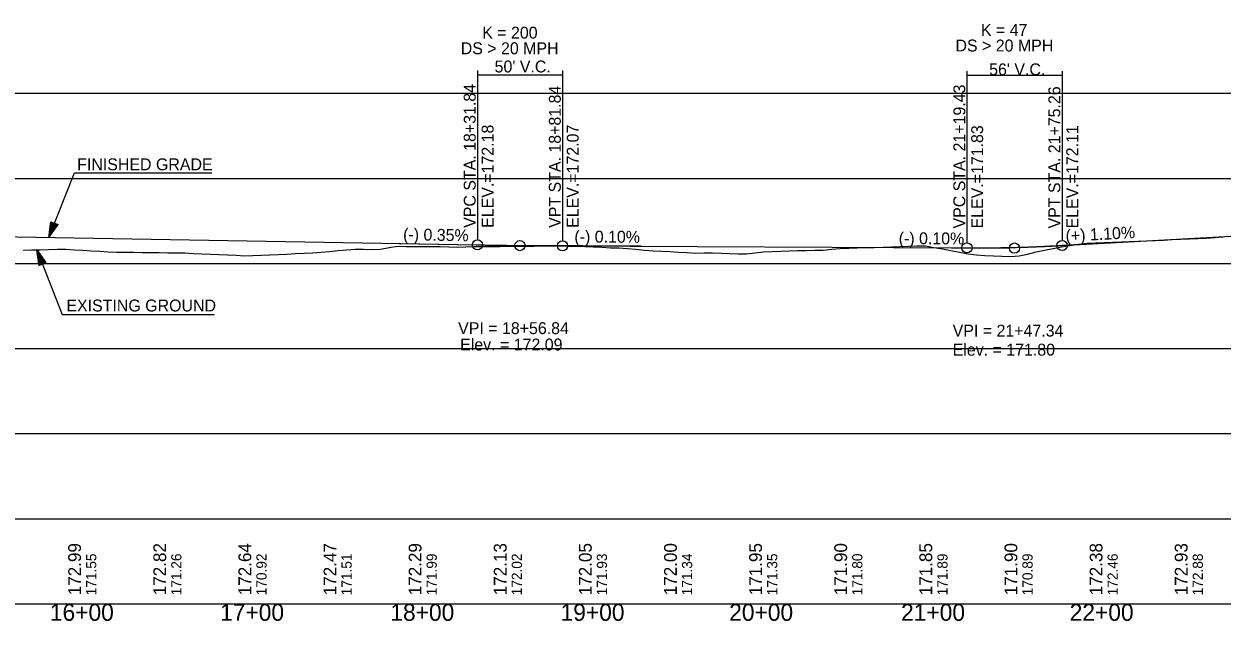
# Model space of a CAD drawing. Extents: x 69 to 2003113, y 512 to 837401.
# Drawn here: x 1891225 to 1891928, y 775879 to 776230 of the extents above; entities that cross this region are included whole.
import ezdxf

# ---------------------------------------------------------------- set-up
doc = ezdxf.new("R2010")
doc.units = 0
for name, color, linetype in [('BR_AUTO DIMENSION', 7, 'Continuous'), ('BR_BORDER LINES', 7, 'Continuous'), ('BR_CENTER LINE BASELINE', 7, 'Continuous'), ('BR_CONCRETE', 7, 'Continuous'), ('BR_GRID DOTS', 7, 'Continuous'), ('BR_GRID LINES', 7, 'Continuous'), ('BR_TEXT', 7, 'Continuous'), ('RD_HC_Points', 7, 'Continuous'), ('RD_PD_ALT1_TrvlWay', 7, 'Continuous'), ('RD_SHT_ID', 7, 'Continuous'), ('RD_SHT_IplotShp', 7, 'Continuous')]:
    doc.layers.add(name, color=color, linetype=linetype)

msp = doc.modelspace()

# ---------------------------------------------------------------- linework, layer by layer
at = {"layer": 'BR_AUTO DIMENSION'}
for p, q in [((1890659.14, 776189.14), (1892786.34, 776189.14)), ((1890659.14, 776139.14), (1892786.34, 776139.14)), ((1890659.14, 776089.14), (1892786.34, 776089.14)), ((1890659.14, 776039.14), (1892786.34, 776039.14)), ((1890659.14, 775989.14), (1892786.34, 775989.14)), ((1890659.14, 775939.14), (1892786.34, 775939.14)), ((1890659.14, 775889.14), (1892786.34, 775889.14))]:
    msp.add_line(p, q, dxfattribs=at)
at = {"layer": 'BR_BORDER LINES'}
for q in [(1892559.14, 775889.14), (1893259.14, 775889.14)]:
    msp.add_line((1890659.14, 775889.14), q, dxfattribs=at)
at = {"layer": 'BR_CENTER LINE BASELINE'}
for p, q in [((1891444.99, 776100.85), (1891512.98, 776099.66)), ((1891586.98, 776099.25), (1891518.98, 776099.59)), ((1891735.48, 776098.51), (1891803.48, 776098.17)), ((1891877.38, 776102.06), (1891809.48, 776098.32))]:
    msp.add_line(p, q, dxfattribs=at)
for centre in [(1891515.98, 776099.61), (1891806.48, 776098.16)]:
    msp.add_circle(centre, 3, dxfattribs=at)
at = {"layer": 'BR_GRID DOTS'}
for p, q in [((1891490.98, 776202.55), (1891490.98, 776103.05)), ((1891490.98, 776200.05), (1891540.98, 776200.05)), ((1891540.98, 776202.55), (1891540.98, 776102.48)), ((1891778.57, 776202.19), (1891778.57, 776101.3)), ((1891778.57, 776199.69), (1891834.4, 776199.69)), ((1891834.4, 776202.19), (1891834.4, 776102.69))]:
    msp.add_line(p, q, dxfattribs=at)
for centre in [(1891490.98, 776100.05), (1891540.98, 776099.48), (1891778.57, 776098.3), (1891834.4, 776099.69)]:
    msp.add_circle(centre, 3, dxfattribs=at)
at = {"layer": 'BR_GRID LINES'}
for p, q in [((1891834.4, 776099.69), (1892067.07, 776112.49)), ((1891084.14, 776107.17), (1891490.98, 776100.05)), ((1891540.98, 776099.48), (1891778.57, 776098.3))]:
    msp.add_line(p, q, dxfattribs=at)
for points in [[(1891490.98, 776100.05), (1891491.98, 776100.03), (1891492.98, 776100.01), (1891493.98, 776100), (1891494.98, 776099.98), (1891495.98, 776099.96), (1891496.98, 776099.95), (1891497.98, 776099.93), (1891498.98, 776099.91), (1891499.98, 776099.9), (1891500.98, 776099.88), (1891501.98, 776099.87), (1891502.98, 776099.85), (1891503.98, 776099.84), (1891504.98, 776099.83), (1891505.98, 776099.81), (1891506.98, 776099.8), (1891507.98, 776099.79), (1891508.98, 776099.77), (1891509.98, 776099.76), (1891510.98, 776099.75), (1891511.98, 776099.73), (1891512.98, 776099.72), (1891513.98, 776099.71), (1891514.98, 776099.7), (1891515.98, 776099.69), (1891516.98, 776099.68), (1891517.98, 776099.67), (1891518.98, 776099.65), (1891519.98, 776099.64), (1891520.98, 776099.63), (1891521.98, 776099.62), (1891522.98, 776099.61), (1891523.98, 776099.61), (1891524.98, 776099.6), (1891525.98, 776099.59), (1891526.98, 776099.58), (1891527.98, 776099.57), (1891528.98, 776099.56), (1891529.98, 776099.55), (1891530.98, 776099.55), (1891531.98, 776099.54), (1891532.98, 776099.53), (1891533.98, 776099.53), (1891534.98, 776099.52), (1891535.98, 776099.51), (1891536.98, 776099.51), (1891537.98, 776099.5), (1891538.98, 776099.49), (1891539.98, 776099.49), (1891540.98, 776099.48)], [(1891778.57, 776098.3), (1891779.68, 776098.29), (1891780.8, 776098.29), (1891781.92, 776098.29), (1891783.03, 776098.28), (1891784.15, 776098.29), (1891785.27, 776098.29), (1891786.38, 776098.29), (1891787.5, 776098.29), (1891788.62, 776098.3), (1891789.73, 776098.31), (1891790.85, 776098.32), (1891791.97, 776098.33), (1891793.08, 776098.34), (1891794.2, 776098.35), (1891795.32, 776098.36), (1891796.43, 776098.38), (1891797.55, 776098.4), (1891798.67, 776098.41), (1891799.78, 776098.43), (1891800.9, 776098.45), (1891802.02, 776098.47), (1891803.13, 776098.5), (1891804.25, 776098.52), (1891805.37, 776098.55), (1891806.48, 776098.58), (1891807.6, 776098.6), (1891808.72, 776098.63), (1891809.83, 776098.67), (1891810.95, 776098.7), (1891812.07, 776098.73), (1891813.18, 776098.77), (1891814.3, 776098.8), (1891815.42, 776098.84), (1891816.53, 776098.88), (1891817.65, 776098.92), (1891818.77, 776098.96), (1891819.88, 776099.01), (1891821, 776099.05), (1891822.12, 776099.1), (1891823.23, 776099.15), (1891824.35, 776099.19), (1891825.47, 776099.24), (1891826.58, 776099.3), (1891827.7, 776099.35), (1891828.82, 776099.4), (1891829.93, 776099.46), (1891831.05, 776099.51), (1891832.17, 776099.57), (1891833.28, 776099.63), (1891834.4, 776099.69)]]:
    msp.add_spline(points, degree=3, dxfattribs=at)
at = {"layer": 'BR_TEXT'}
for points in [[(1891659.14, 776095.88), (1891664.14, 776096.16), (1891669.14, 776096.38), (1891674.14, 776096.53), (1891679.14, 776096.65), (1891684.14, 776096.77), (1891689.14, 776096.89), (1891694.14, 776097.03), (1891699.14, 776097.5), (1891704.14, 776097.95), (1891709.14, 776098.16), (1891714.14, 776098.28), (1891719.14, 776098.41), (1891724.14, 776098.55), (1891729.14, 776098.72), (1891734.14, 776098.89), (1891739.14, 776099.06), (1891744.14, 776099.23), (1891749.14, 776099.4), (1891754.14, 776099.52), (1891759.14, 776098.59), (1891764.14, 776097.69), (1891769.14, 776096.71), (1891774.14, 776095.72), (1891779.14, 776094.82), (1891784.14, 776094.17), (1891789.14, 776093.89), (1891794.14, 776093.64), (1891799.14, 776093.4), (1891804.14, 776093.31), (1891809.14, 776093.58), (1891814.14, 776094.51), (1891819.14, 776095.88), (1891824.14, 776096.97), (1891829.14, 776097.95), (1891834.14, 776098.88), (1891839.14, 776099.74), (1891844.14, 776100.4), (1891849.14, 776101.01), (1891854.14, 776101.22), (1891859.14, 776101.43), (1891864.14, 776101.65), (1891869.14, 776101.86), (1891874.14, 776102.07), (1891879.14, 776102.28), (1891884.14, 776102.49), (1891889.14, 776102.7), (1891894.14, 776102.91), (1891899.14, 776103.13), (1891904.14, 776103.34), (1891909.14, 776103.55), (1891914.14, 776103.76), (1891919.14, 776104.02), (1891924.14, 776104.4), (1891929.14, 776104.78)], [(1891224.14, 776096.91), (1891229.14, 776097.06), (1891234.14, 776097.2), (1891239.14, 776097.35), (1891244.14, 776097.5), (1891249.14, 776097.45), (1891254.14, 776097.16), (1891259.14, 776096.87), (1891264.14, 776096.58), (1891269.14, 776096.29), (1891274.14, 776096.01), (1891279.14, 776095.85), (1891284.14, 776095.78), (1891289.14, 776095.71), (1891294.14, 776095.64), (1891299.14, 776095.57), (1891304.14, 776095.5), (1891309.14, 776095.43), (1891314.14, 776095.35), (1891319.14, 776095.28), (1891324.14, 776095.06), (1891329.14, 776094.83), (1891334.14, 776094.61), (1891339.14, 776094.38), (1891344.14, 776094.15), (1891349.14, 776093.92), (1891354.14, 776093.69), (1891359.14, 776093.74), (1891364.14, 776093.98), (1891369.14, 776094.21), (1891374.14, 776094.44), (1891379.14, 776094.68), (1891384.14, 776094.91), (1891389.14, 776095.14), (1891394.14, 776095.39), (1891399.14, 776095.77), (1891404.14, 776096.2), (1891409.14, 776096.69), (1891414.14, 776097.07), (1891419.14, 776097.46), (1891424.14, 776097.47), (1891429.14, 776097.42), (1891434.14, 776097.57), (1891439.14, 776098.46), (1891444.14, 776099.23), (1891449.14, 776099.19), (1891454.14, 776099.15), (1891459.14, 776099.11), (1891464.14, 776099.07), (1891469.14, 776099.03), (1891474.14, 776098.9), (1891479.14, 776098.68), (1891484.14, 776098.86), (1891489.14, 776099.05), (1891494.14, 776099.12), (1891499.14, 776099.15), (1891504.14, 776099.18), (1891509.14, 776099.22), (1891514.14, 776099.27), (1891519.14, 776099.32), (1891524.14, 776099.37), (1891529.14, 776099.41), (1891534.14, 776099.46), (1891539.14, 776099.48), (1891544.14, 776099.37), (1891549.14, 776099.21), (1891554.14, 776099.03), (1891559.14, 776098.81), (1891564.14, 776098.66), (1891569.14, 776098.39), (1891574.14, 776098.23), (1891579.14, 776097.98), (1891584.14, 776097.5), (1891589.14, 776097.03), (1891594.14, 776096.6), (1891599.14, 776096.32), (1891604.14, 776096.17), (1891609.14, 776095.86), (1891614.14, 776095.51), (1891619.14, 776095.25), (1891624.14, 776095.32), (1891629.14, 776095.3), (1891634.14, 776095.17), (1891639.14, 776094.92), (1891644.14, 776094.72), (1891649.14, 776094.79), (1891654.14, 776095.36), (1891659.14, 776095.88)]]:
    msp.add_lwpolyline(points, dxfattribs=at)
at = {"layer": 'RD_PD_ALT1_TrvlWay'}
for p, q in [((1891239.29, 776104.45), (1891254.25, 776142.41)), ((1891254.25, 776142.41), (1891335.03, 776142.41)), ((1891239.29, 776104.45), (1891240.5, 776113.65)), ((1891242.59, 776112.82), (1891239.29, 776104.45)), ((1891239.29, 776104.45), (1891244.68, 776112)), ((1891240.5, 776113.65), (1891244.68, 776112)), ((1891232.13, 776097.15), (1891247.1, 776059.19)), ((1891235.44, 776088.77), (1891232.13, 776097.15)), ((1891232.13, 776097.15), (1891237.53, 776089.6)), ((1891232.13, 776097.15), (1891233.34, 776087.95)), ((1891233.34, 776087.95), (1891237.53, 776089.6)), ((1891247.1, 776059.19), (1891336.28, 776059.19))]:
    msp.add_line(p, q, dxfattribs=at)
for points in [[(1891242.49, 776112.74), (1891239.42, 776104.95), (1891242.46, 776112.82), (1891239.49, 776105.34), (1891242.36, 776112.82), (1891239.52, 776105.61), (1891242.25, 776112.84), (1891239.55, 776105.94), (1891242.17, 776112.89), (1891239.62, 776106.43), (1891242.05, 776112.96), (1891239.71, 776106.96), (1891241.94, 776112.96), (1891239.76, 776107.35), (1891241.86, 776113.01), (1891239.82, 776107.81), (1891241.75, 776113), (1891239.88, 776108.21), (1891241.69, 776113.1), (1891239.92, 776108.55), (1891241.55, 776113.11), (1891239.97, 776109.05), (1891241.46, 776113.17), (1891240.09, 776109.65), (1891241.36, 776113.23), (1891240.09, 776110.07), (1891241.26, 776113.27), (1891240.18, 776110.69), (1891241.14, 776113.28), (1891240.28, 776111.19), (1891241.04, 776113.38), (1891240.33, 776111.63), (1891240.94, 776113.38), (1891240.37, 776112.04), (1891240.85, 776113.47), (1891240.44, 776112.53), (1891240.74, 776113.43), (1891240.52, 776113.08), (1891240.62, 776113.44)], [(1891239.57, 776104.97), (1891242.61, 776112.7), (1891239.73, 776105.23), (1891242.72, 776112.66), (1891239.88, 776105.47), (1891242.8, 776112.66), (1891240.06, 776105.67), (1891242.86, 776112.62), (1891240.27, 776105.94), (1891242.95, 776112.6), (1891240.44, 776106.19), (1891243.02, 776112.57), (1891240.66, 776106.48), (1891243.12, 776112.56), (1891240.9, 776106.84), (1891243.23, 776112.49), (1891241.11, 776107.16), (1891243.31, 776112.5), (1891241.34, 776107.49), (1891243.39, 776112.45), (1891241.58, 776107.8), (1891243.48, 776112.41), (1891241.82, 776108.15), (1891243.53, 776112.33), (1891242.14, 776108.6), (1891243.63, 776112.34), (1891242.37, 776108.89), (1891243.71, 776112.34), (1891242.66, 776109.27), (1891243.79, 776112.27), (1891242.9, 776109.68), (1891243.88, 776112.22), (1891243.13, 776109.99), (1891243.97, 776112.12), (1891243.38, 776110.27), (1891244.04, 776112.1), (1891243.66, 776110.74), (1891244.18, 776112.12), (1891243.85, 776111.01), (1891244.32, 776112.06), (1891244.03, 776111.18), (1891244.43, 776111.92), (1891244.55, 776111.97), (1891244.39, 776111.93)], [(1891235.33, 776088.85), (1891232.26, 776096.65), (1891235.3, 776088.78), (1891232.33, 776096.26), (1891235.2, 776088.78), (1891232.36, 776095.99), (1891235.09, 776088.76), (1891232.39, 776095.66), (1891235.01, 776088.71), (1891232.46, 776095.17), (1891234.9, 776088.64), (1891232.55, 776094.64), (1891234.78, 776088.63), (1891232.61, 776094.24), (1891234.7, 776088.58), (1891232.67, 776093.79), (1891234.59, 776088.6), (1891232.72, 776093.39), (1891234.53, 776088.5), (1891232.76, 776093.04), (1891234.4, 776088.48), (1891232.82, 776092.54), (1891234.3, 776088.43), (1891232.93, 776091.95), (1891234.2, 776088.37), (1891232.94, 776091.53), (1891234.1, 776088.33), (1891233.02, 776090.9), (1891233.98, 776088.32), (1891233.12, 776090.4), (1891233.88, 776088.22), (1891233.17, 776089.96), (1891233.78, 776088.22), (1891233.21, 776089.56), (1891233.7, 776088.13), (1891233.29, 776089.07), (1891233.58, 776088.16), (1891233.36, 776088.52), (1891233.47, 776088.16)], [(1891232.41, 776096.63), (1891235.45, 776088.9), (1891232.57, 776096.37), (1891235.56, 776088.94), (1891232.72, 776096.13), (1891235.64, 776088.93), (1891232.91, 776095.92), (1891235.7, 776088.98), (1891233.11, 776095.66), (1891235.8, 776089), (1891233.29, 776095.41), (1891235.87, 776089.02), (1891233.5, 776095.12), (1891235.96, 776089.04), (1891233.75, 776094.75), (1891236.07, 776089.1), (1891233.95, 776094.43), (1891236.16, 776089.1), (1891234.18, 776094.1), (1891236.24, 776089.15), (1891234.42, 776093.8), (1891236.32, 776089.18), (1891234.66, 776093.45), (1891236.37, 776089.26), (1891234.98, 776093), (1891236.47, 776089.26), (1891235.21, 776092.71), (1891236.56, 776089.25), (1891235.51, 776092.32), (1891236.63, 776089.32), (1891235.75, 776091.92), (1891236.73, 776089.38), (1891235.97, 776091.61), (1891236.81, 776089.47), (1891236.22, 776091.32), (1891236.88, 776089.5), (1891236.51, 776090.86), (1891237.03, 776089.48), (1891236.69, 776090.59), (1891237.17, 776089.53), (1891236.88, 776090.42), (1891237.27, 776089.68), (1891237.39, 776089.62), (1891237.24, 776089.66)]]:
    msp.add_lwpolyline(points, dxfattribs=at)

# ---------------------------------------------------------------- texts
at = {"layer": 'BR_CENTER LINE BASELINE'}
for s, rotation, p in [('(-) 0.35%', 358.99742, (1891447.31, 776102.81)), ('(-) 0.10%', 359.71353, (1891547.95, 776101.45)), ('(-) 0.10%', 359.71353, (1891738.45, 776100.5)), ('(+) 1.10%', 3.1481, (1891836.67, 776101.82))]:
    msp.add_text(s, height=7, rotation=rotation, dxfattribs=at).set_placement(p)
at = {"layer": 'BR_CONCRETE'}
for s, height, p in [('VPC STA. 18+31.84 ', 7, (1891489.98, 776110.05)), ('VPT STA. 18+81.84 ', 7, (1891539.98, 776110.05)), ('VPC STA. 21+19.43 ', 7, (1891777.57, 776109.69)), ('VPT STA. 21+75.26 ', 7, (1891833.4, 776109.69)), ('ELEV.=172.18', 7, (1891500.48, 776110.05)), ('ELEV.=172.07', 7, (1891550.48, 776110.05)), ('ELEV.=171.83', 7, (1891788.07, 776109.69)), ('ELEV.=172.11', 7, (1891843.9, 776109.69)), ('171.55', 6, (1891267.14, 775894.14)), ('171.26', 6, (1891317.14, 775894.14)), ('170.92', 6, (1891367.14, 775894.14)), ('171.51', 6, (1891417.14, 775894.14)), ('171.99', 6, (1891467.14, 775894.14)), ('172.02', 6, (1891517.14, 775894.14)), ('171.93', 6, (1891567.14, 775894.14)), ('171.34', 6, (1891617.14, 775894.14)), ('171.35', 6, (1891667.14, 775894.14)), ('171.80', 6, (1891717.14, 775894.14)), ('171.89', 6, (1891767.14, 775894.14)), ('170.89', 6, (1891817.14, 775894.14)), ('172.46', 6, (1891867.14, 775894.14)), ('172.88', 6, (1891917.14, 775894.14))]:
    msp.add_text(s, height=height, rotation=90, dxfattribs=at).set_placement(p)
at = {"layer": 'BR_GRID DOTS'}
for s, p in [('K = 200', (1891493.81, 776221.26)), ('K = 47', (1891786.76, 776222.87)), ('DS > 20 MPH', (1891481.2, 776212.08)), ('DS > 20 MPH', (1891771.8, 776213.69)), ("50' V.C.", (1891501.1, 776201.37)), ("56' V.C.", (1891791.6, 776199.69))]:
    msp.add_text(s, height=7, dxfattribs=at).set_placement(p)
at = {"layer": 'RD_HC_Points'}
for s, p in [('172.99', (1891258.14, 775894.14)), ('172.82', (1891308.14, 775894.14)), ('172.64', (1891358.14, 775894.14)), ('172.47', (1891408.14, 775894.14)), ('172.29', (1891458.14, 775894.14)), ('172.13', (1891508.14, 775894.14)), ('172.05', (1891558.14, 775894.14)), ('172.00', (1891608.14, 775894.14)), ('171.95', (1891658.14, 775894.14)), ('171.90', (1891708.14, 775894.14)), ('171.85', (1891758.14, 775894.14)), ('171.90', (1891808.14, 775894.14)), ('172.38', (1891858.14, 775894.14)), ('172.93', (1891908.14, 775894.14))]:
    msp.add_text(s, height=7.5, rotation=90, dxfattribs=at).set_placement(p)
at = {"layer": 'RD_PD_ALT1_TrvlWay'}
for s, p in [('FINISHED GRADE', (1891255.89, 776143.87)), ('EXISTING GROUND', (1891249.56, 776060.92))]:
    msp.add_text(s, height=7, dxfattribs=at).set_placement(p)
at = {"layer": 'RD_SHT_ID'}
for s, p in [('16+00', (1891239.85, 775879.14)), ('17+00', (1891339.85, 775879.14)), ('18+00', (1891439.85, 775879.14)), ('19+00', (1891539.85, 775879.14)), ('20+00', (1891638.89, 775879.14)), ('21+00', (1891739.85, 775879.14)), ('22+00', (1891838.89, 775879.14))]:
    msp.add_text(s, height=10, dxfattribs=at).set_placement(p)
at = {"layer": 'RD_SHT_IplotShp'}
for s, p in [('VPI = 18+56.84', (1891479.67, 776047.61)), ('VPI = 21+47.34', (1891770.17, 776046.16)), ('Elev. = 172.09', (1891480.85, 776037.99)), ('Elev. = 171.80', (1891770.17, 776034.97))]:
    msp.add_text(s, height=7, dxfattribs=at).set_placement(p)

doc.saveas('drawing.dxf')
